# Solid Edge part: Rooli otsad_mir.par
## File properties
Author: KULL
Template: Iso Metric Part.par
Last saved by: KULL
Revision: 2
Application: Solid Edge
Accuracy: 0,990
Username: KULL
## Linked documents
Rooli otsad.par
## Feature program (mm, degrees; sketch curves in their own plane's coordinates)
part copy "CopiedPart_1"
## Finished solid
Body 1: solid body, 12 faces, 11 edges, 0 vertices.
  Faces by surface: torus 5, sphere 4, cylinder 3
  Edges by curve: circle 11
Bounding box of the edges (mm; curved faces can reach further): 6.889 x 50.693 x 13.153, from (-25.2222, -108.3233, 17.5983) to (-18.3328, -57.6299, 30.751).
Cylindrical faces by radius (mm): R1.5 x1, R2 x1, R2.5 x1
Toroidal faces (ring radius, tube radius in mm): R2.3 r0.3 x1, R2.4 r0.4 x1, R2.9 r0.4 x1, R3.5 r2 x2
Spherical faces by radius (mm): R2.5 x1, R3 x1, R4 x2
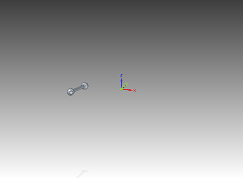
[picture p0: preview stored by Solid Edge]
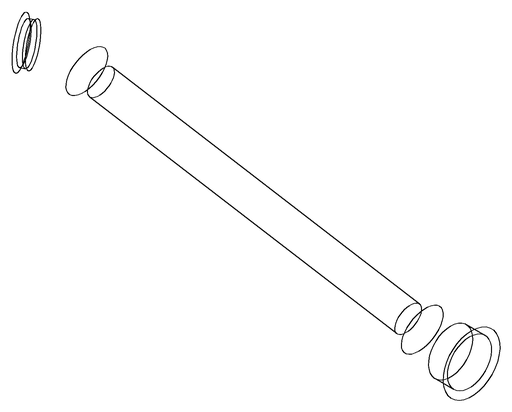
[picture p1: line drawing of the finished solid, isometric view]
